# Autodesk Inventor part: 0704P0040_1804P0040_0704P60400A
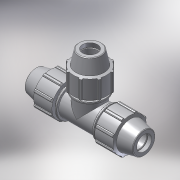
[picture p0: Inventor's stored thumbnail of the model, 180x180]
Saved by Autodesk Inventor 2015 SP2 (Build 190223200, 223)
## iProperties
Created: 2017-02
Part Number: 0704P0040_1804P0040_0704P60400A
Material: PVC-Piping
Description: PLASSON REPAIR TEE 40
Document SubType Name: Modeling
Designer: KIM
Mass: 92.6774 g
Surface Area: 199.44 cm^2
Volume: 66.1981 cm^3
Density: 1.4 g/cm^3
Appearance: Smooth - White
Author: Кирилл
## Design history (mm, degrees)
derived "0704P0.ipt"
feature "Solid1::0704P0.ipt"
tag "TaggingFeature1"
body "Solid1"
other parameters: "d4" = 9.25, "d5" = 27.75, "d7" = 82, "d11" = 3.7, "d13" = 120 deg, "d15" = 12 deg, "d16" = 71.34, "d18" = 2, "d19" = 35 deg, "d20" = 17.5 deg, "d21" = 76.26, "d23" = 0, "d25" = 360 deg, "d27" = 1.64, "d33" = 0.8, "d42" = 38.85, "d43" = 2.46, "d46" = 1.2, "d63" = 86, "d67" = 61.5, "d77" = 82, "d78" = 12 deg, "d79" = 111, "d80" = 120 deg, "d82" = 9.25, "d85" = 61.5, "d86" = 71.34, "d87" = 3.7, "d88" = 3.7, "d89" = 27.75, "d90" = 38.85, "d96" = 11.1, "d98" = 76.26, "d99" = 35 deg, "d100" = 17.5 deg, "d102" = 0, "d103" = 1.64, "d107" = 360 deg, "d109" = 1.2, "d112" = 2, "d118" = 360 deg, "d121" = 0, "d128" = 221, "d131" = 36, "d132" = 36, "d133" = 86, "d134" = 1.72, "d135" = 11.1, "d152" = 0, "d154" = 0, "d156" = 0, "d158" = 0, "E_" = 82, "A_" = 111, "l_" = 86, "H_" = 221
